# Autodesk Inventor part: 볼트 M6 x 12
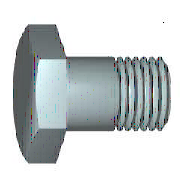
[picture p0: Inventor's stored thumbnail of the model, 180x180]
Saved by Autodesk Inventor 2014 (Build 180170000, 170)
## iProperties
IsCustomPart: 0
Created: 2012-02
Part Number: 볼트 M6 x 12
Material: 스테인리스강
Description: 6각 머리 나사. 제품 등급 C
Document SubType Name: Modeling
Standard: ISO 4018
Designer: mduedu
Standard Revision: Third edition 1999-08-15
Standards Organization: ISO
Language: ko-KR
Size Designation: M6 x 12
Categories: <MemberInstance><Categories><Category DisplayName="조임쇠" InternalName="e4da775c-781d-43d5-af7c-5136215cf5a6" Mnemonic="FSTN"><Category DisplayName="볼트" InternalN
Density: 8.08 g/cm^3
Mass: 5.5158 g
Surface Area: 5.26064 cm^2
Volume: 0.682649 cm^3
Appearance: 반광택
Author: mduedu
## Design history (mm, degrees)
node "WorkPlane1"
node "WorkPoint1"
node "MSC_A1"
node "MSC_PF1"
node "MSC_PT1"
body "Solid1"
node "스케치1"
sketch "스케치2"
  geometry: L1 (-5, 2.887)-(-5, -2.887); L2 (0, 5.773)-(-5, 2.887); L3 (5, 2.887)-(0, 5.773); L4 (5, -2.887)-(5, 2.887); L5 (0, -5.773)-(5, -2.887); L6 (-5, -2.887)-(0, -5.773); C1 r 5 at (0, 0); 1 further point
  constraints: 12 end point, 6 tangent, 2 parallel, 2 vertical, 1 centre point
  dimensions: "d1" = 10 diameter of C1 (= ParS); "d29" = 0 distance of point (0, 0) C1.centre; "d30" = 0 distance of C1.centre point (0, 0)
extrude "돌출1" new body sketch "스케치2" distance "d6" = 4 (= ParK); taper "d7" = 0 deg
revolve "회전1" stored, may be unused: angle "d14" = 360 deg
revolve "회전2" stored, may be unused: angle "d21" = 360 deg
chamfer "모따기1" distance "d22" = 0.5 (= 0.5 x PTC); stored, may be unused: second distance "d23" = 0.5 (= 0.5 x PTC), angle "d39" = 45 deg
fillet "모깎기1" dims "d24" = 0.25 (= r)
feature "스레드1" dims "d32" = 0, "b" = 10.5 (= NLG - 1.5 x PTC)
sketch "스케치3"
  geometry: L1 (5, 4)-(5.873, 4); L2 (5.873, 3.496)-(5, 4); L3 (5.873, 4)-(5.873, 3.496); L4 (0, -0.8)-(0, 4.8) reference; L5 (5.773, 0)-(5.773, 4) reference
  constraints: 6 end point, 1 horizontal, 1 vertical
  dimensions: "d25" = 0.1 distance between parallel lines of L5 L3; "d26" = 0 distance from line of L5.end L1; "d27" = 60 deg angle of L3 L2; "d28" = 5 distance from line of L4 L1.start (= 0.5 x ParS)
sketch "스케치4"
  geometry: L1 (0, -12)-(0, 0); L2 (-3, -12)-(0, -12); L3 (-3, 0)-(-3, -12); L4 (0, 0)-(-3, 0); L5 (0, -12)-(0, 0); L6 (-3.6, 0)-(0.6, 0) reference; L7 (0, -14.4)-(0, 2.4) reference
  constraints: 10 end point, 2 horizontal, 2 vertical
  dimensions: "d18" = 3 distance of L1.start L2.start (= 0.5 x NND); "d20" = 12 distance of L3.start L2.start (= NLG); "d33" = 0 distance between parallel lines of L7 L1; "d34" = 0 distance between parallel lines of L6 L4
other parameters: "NND" = 6 [user parameter; used in 2 equation terms], "NLG" = 12 [user parameter; used in 2 equation terms], "PTC" = 1 [user parameter; used in 3 equation terms], "ParK" = 4 [user parameter; used in 1 equation term], "ParS" = 10 [user parameter; used in 3 equation terms], "msp_es" = 5.77367 (= 0.577367 x ParS) [user parameter], "r" = 0.25 [user parameter; used in 1 equation term], "d2" = 15 (derived), "d4" = 17.32102 (derived), "d8" = 15 (derived), "d10" = 0 (derived), "d12" = 30 deg (derived), "d15" = 0 (derived), "d37" = 0, "d38" = 0, "d40" = 0, "d41" = 0, "d42" = 0, "THREADDIA" = 6 (= NND) [user parameter]
